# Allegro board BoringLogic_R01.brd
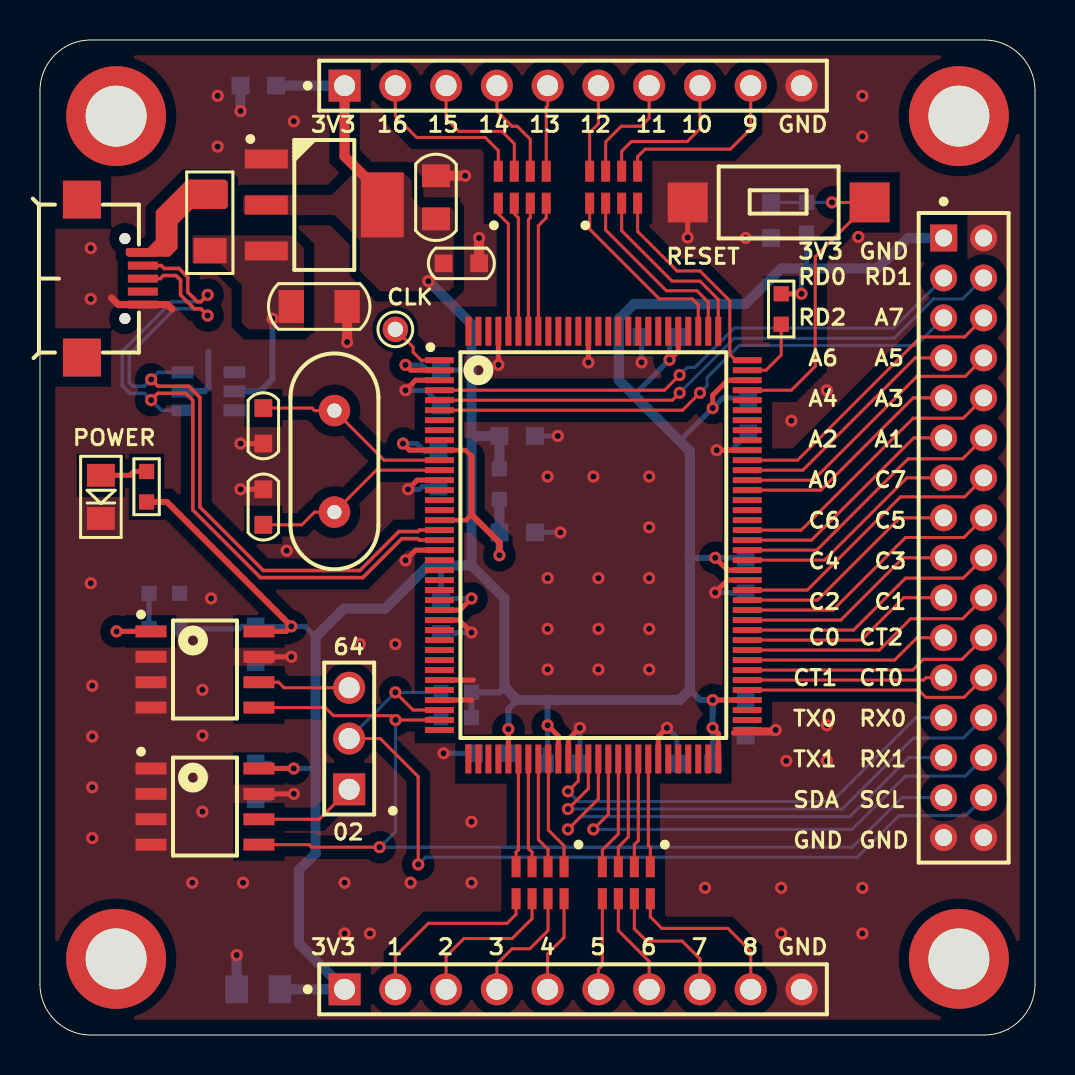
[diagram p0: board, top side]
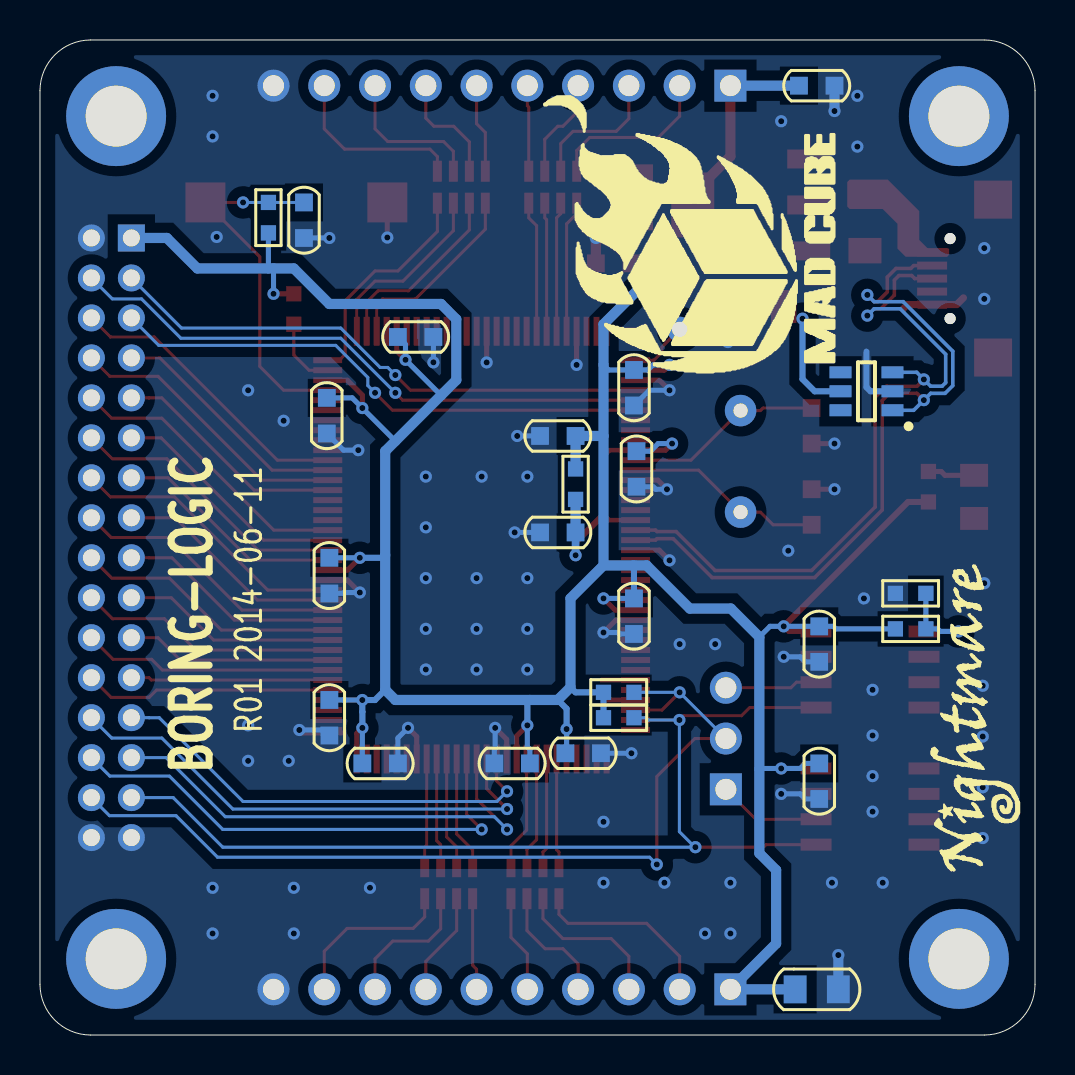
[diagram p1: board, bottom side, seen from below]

Outline 49.78 x 49.78 mm; copper layers: TOP, BOTTOM. Coordinates in mm from the lower left corner of the outline.
Outline path: 0,47.24 0,2.54 arc(0.74,0.74) 2.54,0 47.24,0 arc(49.04,0.74) 49.78,2.54 49.78,47.24 arc(49.04,49.04) 47.24,49.78 2.54,49.78 arc(0.74,49.04) 0,47.24

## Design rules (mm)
net group DIFF_USB: nets USB_DM USB_DP

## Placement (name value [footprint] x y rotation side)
C1  0.1uF  [C0603]  10.79 12.7 180 bottom
C2  22uF  [C1206]  13.97 36.45 90 top
C3  10uF  [C0805]  19.81 41.91 180 top
C4  0.1uF  [C0603]  21.08 38.61 90 top
C5  22pF  [C0603]  11.18 26.42 0 top
C6  0.1uF NC  [C0603]  10.79 19.56 180 bottom
C7  22pF  [C0603]  11.18 30.48 180 top
C8  1uF  [C0603]  36.58 40.77 0 bottom
C9  10uF  [C0805]  10.92 2.29 90 bottom
C10  0.1uF  [C0603]  10.92 47.5 90 bottom
C11  0.1uF  [C0603]  35.31 22.99 180 bottom
C12  0.1uF  [C0603]  22.61 14.1 90 bottom
C13  0.1uF  [C0603]  30.99 34.92 90 bottom
C14  0.1uF  [C0603]  20.07 32.38 180 bottom
C15  0.1uF  [C0603]  26.16 13.59 270 bottom
C16  0.1uF  [C0603]  35.43 30.99 180 bottom
C17  0.1uF  [C0603]  20.07 20.95 180 bottom
C18  0.1uF  [C0603]  32.77 13.59 90 bottom
C19  0.1uF  [C0603]  35.31 15.88 180 bottom
C20  1uF  [C0603]  23.88 29.97 270 bottom
C21  0.1uF  [C0603]  23.88 25.15 270 bottom
C22  0.1uF  [C0603]  19.94 28.32 180 bottom
D1  SRV05 NC  [SOT23-6]  8.43 32.21 0 bottom
F1  1.5A  [R1206]  8.51 40.64 0 top
FB1  120R  [R0603]  22.99 28.32 270 bottom
J1  LOGIC_CON_A  [SIP10]  15.24 2.29 0 top
J2  LOGIC_CON_B  [SIP10]  15.24 47.5 0 top
J3  EXT_IOA  [SIP16X2_2MM]  45.21 39.88 270 top
J4  JUMPER  [SIP3]  15.47 12.29 90 top
LED1  PWR  [LED0805]  3.05 26.92 0 top
NOREF  -  []  7.52 30.63 90 bottom
NOREF#2  -  []  3.15 15.57 90 bottom
P1  MicroUSB Female  [USB_MICRO_F_SMT]  -0.05 37.85 270 top
R1  2.2K  [R0603]  20.07 17.14 0 bottom
R2  2.2K  [R0603]  20.07 15.88 0 bottom
R5  2.2K NC  [R0603]  5.46 20.32 0 bottom
R7  2.2K NC  [R0603]  6.99 22.1 180 bottom
R9  510R  [R0603]  5.33 28.19 270 top
R11  100K  [R0603]  38.35 41.66 270 bottom
R12  100K  [R0603]  37.08 35.56 90 top
RN1  100R  [RN0603]  29.34 7.62 270 top
RN2  100R  [RN0603]  25.02 7.62 270 top
RN3  100R  [RN0603]  24.13 42.42 90 top
RN4  100R  [RN0603]  28.7 42.42 90 top
SW1  RESET  [SW_2P_SMT]  36.96 41.66 0 top
TH1  TH_3mm  [TH3_0]  3.81 45.97 0 top
TH2  TH_3mm  [TH3_0]  45.97 45.97 0 top
TH3  TH_3mm  [TH3_0]  45.97 3.81 0 top
TH4  TH_3mm  [TH3_0]  3.81 3.81 0 top
TP1  VO  [TP5030]  17.78 35.31 0 top
U1  CY7C68013A  [QFP128A]  27.69 24.51 0 top
U2  AT24C02  [SO8]  8.26 11.43 0 top
U3  LM1117  [SOT223]  14.22 41.53 0 top
U4  AT24C64 NC  [SO8]  8.26 18.29 0 top
Y1  HC-49S 24M  [HC-49S]  14.73 28.7 90 top

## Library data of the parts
C1 C4-C22 = CAP NP
C2 C3 = CAP_CE_0603
D1 = SRV05-4
F1 = FUSE
FB1 = FB
J1 J2 = HEADER 10
J3 = HEADER 16X2
J4 = HEADER 3
LED1 = LED_0805
P1 = CON_USB_MICRO_F: User Part Number: pn; Tolerance: RichardLC
R1 R2 R5 R7 R9 R11 R12 = R
RN1-RN4 = 8P4R_0402
SW1 = SW PUSHBUTTON
TH1-TH4 = THROUGH_HOLE
TP1 = T POINT R
U1 = CY7C68013A_128P
U2 U4 = AT24C512
U3 = LM1117
Y1 = HC-49S

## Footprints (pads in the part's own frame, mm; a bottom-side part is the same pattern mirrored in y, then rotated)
C0603
  rect 0.889x0.889 smd: 1(0,0.889) 2(0,-0.889)
C0805
  rect 1.397x1.143 smd: 1(0,1.079) 2(0,-1.079)
C1206
  rect 1.651x1.27 smd: 1(0,1.397) 2(0,-1.397)
HC-49S
  round 1.575 hole 0.711: 1(-2.54,0) 2(2.54,0)
LED0805
  rect 1.397x1.143 smd: 1(0,1.079) 2(0,-1.079)
QFP128A
  rect 1.45x0.3 smd: 1(-7.7,9.25) 2(-7.7,8.75) 3(-7.7,8.25) 4(-7.7,7.75) 5(-7.7,7.25) 6(-7.7,6.75) 7(-7.7,6.25) 8(-7.7,5.75) 9(-7.7,5.25) 10(-7.7,4.75) 11(-7.7,4.25) 12(-7.7,3.75) 13(-7.7,3.25) 14(-7.7,2.75) 15(-7.7,2.25) 16(-7.7,1.75) 17(-7.7,1.25) 18(-7.7,0.75) 19(-7.7,0.25) 20(-7.7,-0.25) 21(-7.7,-0.75) 22(-7.7,-1.25) 23(-7.7,-1.75) 24(-7.7,-2.25) 25(-7.7,-2.75) 26(-7.7,-3.25) 27(-7.7,-3.75) 28(-7.7,-4.25) 29(-7.7,-4.75) 30(-7.7,-5.25) 31(-7.7,-5.75) 32(-7.7,-6.25) 33(-7.7,-6.75) 34(-7.7,-7.25) 35(-7.7,-7.75) 36(-7.7,-8.25) 37(-7.7,-8.75) 38(-7.7,-9.25) 65(7.7,-9.25) 66(7.7,-8.75) 67(7.7,-8.25) 68(7.7,-7.75) 69(7.7,-7.25) 70(7.7,-6.75) 71(7.7,-6.25) 72(7.7,-5.75) 73(7.7,-5.25) 74(7.7,-4.75) 75(7.7,-4.25) 76(7.7,-3.75) 77(7.7,-3.25) 78(7.7,-2.75) 79(7.7,-2.25) 80(7.7,-1.75) 81(7.7,-1.25) 82(7.7,-0.75) 83(7.7,-0.25) 84(7.7,0.25) 85(7.7,0.75) 86(7.7,1.25) 87(7.7,1.75) 88(7.7,2.25) 89(7.7,2.75) 90(7.7,3.25) 91(7.7,3.75) 92(7.7,4.25) 93(7.7,4.75) 94(7.7,5.25) 95(7.7,5.75) 96(7.7,6.25) 97(7.7,6.75) 98(7.7,7.25) 99(7.7,7.75) 100(7.7,8.25) 101(7.7,8.75) 102(7.7,9.25)
  rect 0.3x1.45 smd: 39(-6.25,-10.7) 40(-5.75,-10.7) 41(-5.25,-10.7) 42(-4.75,-10.7) 43(-4.25,-10.7) 44(-3.75,-10.7) 45(-3.25,-10.7) 46(-2.75,-10.7) 47(-2.25,-10.7) 48(-1.75,-10.7) 49(-1.25,-10.7) 50(-0.75,-10.7) 51(-0.25,-10.7) 52(0.25,-10.7) 53(0.75,-10.7) 54(1.25,-10.7) 55(1.75,-10.7) 56(2.25,-10.7) 57(2.75,-10.7) 58(3.25,-10.7) 59(3.75,-10.7) 60(4.25,-10.7) 61(4.75,-10.7) 62(5.25,-10.7) 63(5.75,-10.7) 64(6.25,-10.7) 103(6.25,10.7) 104(5.75,10.7) 105(5.25,10.7) 106(4.75,10.7) 107(4.25,10.7) 108(3.75,10.7) 109(3.25,10.7) 110(2.75,10.7) 111(2.25,10.7) 112(1.75,10.7) 113(1.25,10.7) 114(0.75,10.7) 115(0.25,10.7) 116(-0.25,10.7) 117(-0.75,10.7) 118(-1.25,10.7) 119(-1.75,10.7) 120(-2.25,10.7) 121(-2.75,10.7) 122(-3.25,10.7) 123(-3.75,10.7) 124(-4.25,10.7) 125(-4.75,10.7) 126(-5.25,10.7) 127(-5.75,10.7) 128(-6.25,10.7)
R0603
  rect 0.762x0.762 smd: 1(0,0) 2(1.524,0)
R1206
  rect 1.651x1.27 smd: 1(0,1.397) 2(0,-1.397)
RN0603
  rect 1.05x0.45 smd: 1(-0.8,1.2) 2(-0.8,0.4) 3(-0.8,-0.4) 4(-0.8,-1.2) 5(0.8,-1.2) 6(0.8,-0.4) 7(0.8,0.4) 8(0.8,1.2)
SIP3
  rect 1.6x1.6 hole 1.05: 1(0,0)
  round 1.6 hole 1.05: 2(2.54,0) 3(5.08,0)
SIP10
  rect 1.6x1.6 hole 1.05: 1(0,0)
  round 1.6 hole 1.05: 2(2.54,0) 3(5.08,0) 4(7.62,0) 5(10.16,0) 6(12.7,0) 7(15.24,0) 8(17.78,0) 9(20.32,0) 10(22.86,0)
SIP16X2_2MM
  rect 1.35x1.35 hole 0.85: 1(0,0)
  round 1.35 hole 0.85: 2(0,2) 3(2,0) 4(2,2) 5(4,0) 6(4,2) 7(6,0) 8(6,2) 9(8,0) 10(8,2) 11(10,0) 12(10,2) 13(12,0) 14(12,2) 15(14,0) 16(14,2) 17(16,0) 18(16,2) 19(18,0) 20(18,2) 21(20,0) 22(20,2) 23(22,0) 24(22,2) 25(24,0) 26(24,2) 27(26,0) 28(26,2) 29(28,0) 30(28,2) 31(30,0) 32(30,2)
SO8
  rect 1.55x0.6 smd: 1(-2.7,1.905) 2(-2.7,0.635) 3(-2.7,-0.635) 4(-2.7,-1.905) 5(2.7,-1.905) 6(2.7,-0.635) 7(2.7,0.635) 8(2.7,1.905)
SOT23-6
  rect 1.1x0.6 smd: 1(-1.3,0.95) 2(-1.3,0) 3(-1.3,-0.95) 4(1.3,-0.95) 5(1.3,0) 6(1.3,0.95)
SOT223
  rect 2.15x0.95 smd: 1(-2.9,2.3) 2(-2.9,0) 3(-2.9,-2.3)
  rect 2.15x3.25 smd: 4(2.9,0)
SW_2P_SMT
  rect 2x2 smd: 1(-4.55,0) 2(4.55,0)
TH3_0
  round 5 hole 3.048: 1(0,0)
TP5030
  round 1.27 hole 0.76: 1(0,0)
USB_MICRO_F_SMT
  round 0.55 hole 0.55: (-2,4.3) (2,4.3)
  rect 0.4x1.5 smd: 1(-1.3,5.2) 2(-0.65,5.2) 3(0,5.2) 4(0.65,5.2) 5(1.3,5.2)
  rect 1.9x1.9 smd: 6(-3.95,2.15) 7(3.95,2.15)

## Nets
GND: C1.2 C2.2 C3.2 C4.2 C5.1 C6.2 C7.1 C8.1 C9.2 C10.2 C11.2 C12.2 C13.2 C14.2 C15.2 C16.2 C17.2 C18.2 C19.2 C20.2 C21.2 C22.2 D1.2(GND) J1.10 J2.10 J3.2 J3.31 J3.32 LED1.2(CATHODE) P1.5(GND) R7.1 SW1.1 U1.3(GND#3) U1.13(AGND#13) U1.20(AGND#20) U1.27(GND#27) U1.33(RSVD) U1.35(EA) U1.49(GND#49) U1.58(GND#58) U1.65(GND#65) U1.80(GND#80) U1.93(GND#93) U1.116(GND#116) U1.125(GND#125) U2.1(A0) U2.2(A1) U2.3(NC) U2.4(GND) U2.7(WP) U3.1(GND) U4.2(A1) U4.3(NC) U4.4(GND) U4.7(WP)
VCC3V3A: C21.1 C22.1 FB1.2 U1.10(AVCC#10) U1.17(AVCC#17)
VDD3V3: C1.1 C3.1 C4.1 C6.1 C9.1 C10.1 C11.1 C12.1 C13.1 C14.1 C15.1 C16.1 C17.1 C18.1 C19.1 C20.1 FB1.1 J1.1 J2.1 J3.1 R1.2 R2.2 R5.2 R9.2 R11.2 R12.2 U1.2(VCC#2) U1.26(VCC#26) U1.43(VCC#43) U1.48(VCC#48) U1.64(VCC#64) U1.68(VCC#68) U1.81(VCC#81) U1.100(VCC#100) U1.107(VCC#107) U2.8(VCC) U3.2(OUT) U3.4(PAD) U4.8(VCC)
VDD5V: C2.1 D1.5(VCC) F1.2 U3.3(IN)
CH1: J1.2 RN2.5
CH2: J1.3 RN2.6(5)
CH3: J1.4 RN2.7(5)
CH4: J1.5 RN2.8(5)
CH5: J1.6 RN1.5
CH6: J1.7 RN1.6(5)
CH7: J1.8 RN1.7(5)
CH8: J1.9 RN1.8(5)
CH9: J2.9 RN4.5
CH10: J2.8 RN4.6(5)
CH11: J2.7 RN4.7(5)
CH12: J2.6 RN4.8(5)
CH13: J2.5 RN3.5
CH14: J2.4 RN3.6(5)
CH15: J2.3 RN3.7(5)
CH16: J2.2 RN3.8(5)
CLKOUT: TP1.1(TP) U1.1(CLKOUT)
CTL0: J3.24 U1.69(CTL0/FLAGA)
CTL1: J3.23 U1.70(CTL1/FLAGB)
CTL2: J3.22 U1.71(CTL2/FLAGC)
FD0: RN2.4 U1.44(PB0/FD0)
FD1: RN2.3(4) U1.45(PB1/FD1)
FD2: RN2.2(4) U1.46(PB2/FD2)
FD3: RN2.1(4) U1.47(PB3/FD3)
FD4: RN1.4 U1.54(PB4/FD4)
FD5: RN1.3(4) U1.55(PB5/FD5)
FD6: RN1.2(4) U1.56(PB6/FD6)
FD7: RN1.1(4) U1.57(PB7/FD7)
FD8: RN4.4 U1.102(PD0/FD8)
FD9: RN4.3(4) U1.103(PD1/FD9)
FD10: RN4.2(4) U1.104(PD2/FD10)
FD11: RN4.1(4) U1.105(PD3/FD11)
FD12: RN3.4 U1.121(PD4/FD12)
FD13: RN3.3(4) U1.122(PD5/FD13)
FD14: RN3.2(4) U1.123(PD6/FD14)
FD15: RN3.1(4) U1.124(PD7/FD15)
PA0: J3.13 U1.82(PA0/I\N\T\0\)
PA1: J3.12 U1.83(PA1/I\N\T\1\)
PA2: J3.11 U1.84(PA2/SLOE)
PA3: J3.10 U1.85(PA3/WU2)
PA4: J3.9 U1.89(PA4/FIFOADR0)
PA5: J3.8 U1.90(PA5/FIFOADR1)
PA6: J3.7 U1.91(PA6/PKTEND)
PA7: J3.6 U1.92(PA7/FLAGD/S\L\C\S\)
PC0: J3.21 U1.72(PC0/GPIFADR0)
PC1: J3.20 U1.73(PC1/GPIFADR1)
PC2: J3.19 U1.74(PC2/GPIFADR2)
PC3: J3.18 U1.75(PC3/GPIFADR3)
PC4: J3.17 U1.76(PC4/GPIFADR4)
PC5: J3.16 U1.77(PC5/GPIFADR5)
PC6: J3.15 U1.78(PC6/GPIFADR6)
PC7: J3.14 U1.79(PC7/GPIFADR7)
RDY0: J3.3 U1.4(RDY0/SLRD)
RDY1: J3.4 U1.5(RDY1/SLWR)
RDY2: J3.5 U1.6(RDY2)
RESET#: C8.2 R11.1 SW1.2 U1.99(R\E\S\E\T\)
RXD0: J3.26 U1.51(RXD0)
RXD1: J3.28 U1.53(RXD1)
SCL: J3.30 J4.2 R1.1 U1.36(SCL)
SCL_LG: J4.3 U4.6(SCL)
SCL_S: J4.1 U2.6(SCL)
SDA: J3.29 R2.1 U1.37(SDA) U2.5(SDA) U4.5(SDA)
TXD0: J3.25 U1.50(TXD0)
TXD1: J3.27 U1.52(TXD1)
USB_DM: D1.1(IO1) P1.2(D-) U1.19(DMINUS)
USB_DP: D1.3(IO2) P1.3(D+) U1.18(DPLUS)
WAKEUP: R12.1 U1.101(WAKEUP)
XIN: C5.2 U1.12(XTALIN) Y1.1
XOUT: C7.2 U1.11(XTALOUT) Y1.2
N1173626: F1.1 P1.1(VCC)
N1191686: R5.1 R7.2 U4.1(A0)
N1227883: LED1.1(ANODE) R9.1

Pads without a net: D1 4 6; P1 4 6 7; TH1 1; TH2 1; TH3 1; TH4 1; U1 7 8 9 14 15 16 21 22 23 24 25 28 29 30 31 32 34 38 39 40 41 42 59 60 61 62 63 66 67 86 87 88 94 95 96 97 98 106 108 109 110 111 112 113 114 115 117 118 119 120 126 127 128

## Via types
v1: diameter 0.61, hole 0.305, TOP to BOTTOM, 111 vias

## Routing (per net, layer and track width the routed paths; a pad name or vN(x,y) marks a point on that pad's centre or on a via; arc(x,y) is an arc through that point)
GND: length 70.3
  TOP w0.254: U1.65 v1(36.81,15.26) 36.66,15.11 34.7,15.11 ; U1.20 18.8,24.26 v1(18.29,23.75) ; U1.58 30.94,14.93 v1(31.37,15.37) ; SW1.1 v1(32.41,39.9) ; v1(18.29,32.26) 18.79,32.76 U1.3 ; U1.116 v1(27.44,33.65) ; v1(18.41,27.3) 18.87,27.76 U1.13 ; U2.7 v1(12.7,12.06) ; v1(27.01,15.37) 26.44,14.79 U1.49 ; U1.35 21.59,16.76 ; U1.80 34.4,22.76 v1(33.78,22.14) ; U4.7 v1(12.57,18.92) ; C7.1 v1(10.03,29.59) ; U1.93 v1(33.86,29.26) ; U1.125 v1(22.94,33.53) ; v1(21.59,20.14) 20.97,20.76 U1.27 ; C5.1 v1(10.03,27.3) ; U1.33 21.69,17.76
  TOP w0.356: 3.58,36.88 3.92,36.55 P1.5 6.38,36.55 6.6,36.32
  TOP w0.508: C2.2 v1(15.37,34.67) ; C4.2 v1(21.97,39.88) ; C3.2 v1(21.27,42.99)
  BOTTOM w0.254: C16.2 34.6,29.26 v1(33.86,29.26) ; v1(31.37,15.37) 31.88,14.86 C18.2 ; v1(27.01,15.37) 27.01,14.33 27.05,14.29 C15.2 ; 21.72,14.1 v1(20.19,14.1) ; C11.2 34.6,22.1 34.56,22.14 v1(33.78,22.14) ; C1.2 11.5,11.81 11.75,12.06 v1(12.7,12.06) ; C20.2 v1(25.91,29.97) ; C6.2 11.5,18.67 11.75,18.92 v1(12.57,18.92) ; C19.2 35.58,15.26 v1(36.81,15.26) ; C17.2 20.77,20.07 20.84,20.14 v1(21.59,20.14) ; C13.2 v1(30.1,33.66) ; C8.1 v1(35.31,39.88) ; v1(18.29,32.26) 19.3,32.26 C14.2 ; C21.2 v1(26.04,25.15) ; v1(18.41,27.3) 18.98,27.3 19.1,27.43 C22.2
  BOTTOM w0.305: D1.2 8.23,32.21 8.43,32.41 8.43,34.19
  BOTTOM w0.508: 10.03,47.5 v1(10.03,46.23) ; C9.2 v1(9.84,4)
  vias: v1(2.54,39.37) v1(2.54,36.83) v1(2.54,22.61) v1(2.62,17.48) v1(2.62,14.94) v1(2.62,12.4) v1(2.62,9.86) v1(7.62,7.62) v1(8.13,17.27) v1(8.13,14.99) v1(8.13,12.95) v1(8.13,11.18) v1(8.56,21.84) v1(8.89,46.99) v1(8.89,44.45) v1(10.16,7.62) v1(12.34,24.23) v1(12.7,45.72) v1(15.24,7.62) v1(15.24,5.08) v1(16,19.56) v1(16.51,5.08) v1(17.78,19.56) v1(18.54,7.62) v1(21.59,10.67) v1(21.59,7.62) v1(25.4,27.94) v1(25.4,22.86) v1(25.4,20.32) v1(25.4,18.29) v1(27.69,27.94) v1(27.94,22.86) v1(27.94,20.32) v1(27.94,18.29) v1(30.48,27.94) v1(30.48,25.4) v1(30.48,22.86) v1(30.48,20.32) v1(30.48,18.29) v1(33.27,7.37) v1(37.08,7.37) v1(37.08,5.08) v1(37.34,13.72) v1(37.59,30.73) v1(39.37,32.26) v1(39.37,15.49) v1(39.37,13.72) v1(40.94,39.93) v1(41.15,46.99) v1(41.15,44.96) v1(41.15,7.37) v1(41.15,5.08)
VCC3V3A: length 15.7
  TOP w0.229: 21.59,28.96 21.28,29.26 U1.10 ; U1.17 21.32,25.76 21.59,26.04
  TOP w0.254: v1(18.16,29.59) 18.49,29.26 U1.10
  TOP w0.305: 21.59,28.96 21.59,26.04 22.99,24.64 v1(22.99,24)
  BOTTOM w0.254: C22.1 19.24,29.21 18.86,29.59 v1(18.16,29.59)
  BOTTOM w0.381: C21.1 v1(22.99,24)
  BOTTOM w0.508: C21.1 FB1.2
VDD3V3: length 191.5
  TOP w0.254: v1(21.59,21.84) 21.01,21.26 U1.26 ; v1(33.66,31.37) 33.66,32.01 34.4,32.76 U1.100 ; R12.2 v1(38.1,37.08) ; U1.81 34.4,23.26 v1(33.78,23.88) ; U1.68 v1(33.66,16.76) ; U4.8 12.32,20.19 v1(12.57,20.45) ; U1.2 18.55,33.26 v1(18.29,33.53) ; 10.96,13.34 v1(12.7,13.34) ; v1(33.66,15.37) 33.94,15.09 U1.64 ; U1.48 25.94,14.96 v1(25.4,15.49) ; v1(31.5,33.78) 31.94,34.22 U1.107 ; U1.43 v1(23.44,15.31)
  TOP w0.305: v1(12.57,20.45) 6.35,26.67 R9.2
  TOP w0.508: U3.4 17.12,42.08 15.24,43.96 J2.1
  BOTTOM w0.254: 21.59,33.53 21.34,33.27 C14.1 19.36,33.27 19.11,33.53 v1(18.29,33.53) ; v1(38.1,37.08) 38.1,38.35 ; v1(23.44,15.31) 23.44,14.16 C12.1 ; 32,29.72 v1(33.66,31.37) 34.16,31.88 C16.1 ; v1(33.78,23.88) C11.1 ; R11.2 38.35,38.35 ; 13.79,19.91 13.26,20.45 v1(12.57,20.45) C6.1 10.09,20.45 9.97,20.32 R5.2 ; 13.79,13.31 13.77,13.34 v1(12.7,13.34) 11.75,13.34 11.5,13.59 C1.1 ; C15.1 25.27,14.29 25.4,14.42 v1(25.4,15.49) ; 29.72,32 v1(31.5,33.78) 31.5,34.54 C13.1 ; v1(33.66,15.37) C18.1 ; v1(21.59,21.84) C17.1 ; C19.1 34.6,16.76 34.6,16.76 v1(33.66,16.76)
  BOTTOM w0.305: v1(33.66,15.37) 33.66,16.17 33.66,16.17 v1(33.66,16.76) 33.02,16.76 32.51,17.27 ; C17.1 20.07,23.5 ; 23.24,17.4 22.99,17.14 R1.2 R2.2 ; 23.88,16.76 23.44,16.32 v1(23.44,15.31) ; 25.27,16.76 25.4,16.64 v1(25.4,15.49) ; v1(33.78,23.88) 32.64,23.88 32.51,24
  BOTTOM w0.508: 21.59,23.5 21.59,29.97 ; 21.59,23.5 19.43,23.5 17.27,21.34 15.21,21.34 13.79,19.91 13.79,9.09 12.95,8.26 12.95,4.57 J1.1 C9.1 ; 21.59,23.5 23.24,21.84 23.24,17.4 23.88,16.76 32,16.76 32.51,17.27 32.51,29.21 28.96,32.77 28.96,35.81 29.72,36.58 35.31,36.58 37.08,38.35 41.91,38.35 43.43,39.88 J3.1 ; 21.59,29.97 C20.1 FB1.1 ; 21.59,29.97 21.59,35.56 v1(19.43,37.72) ; C10.1 J2.1
VDD5V: length 5.2
  BOTTOM w0.305: v1(11.63,35.84) 11.63,32.82 11.02,32.21 D1.5
CH1: length 9.3
  TOP w0.152: J1.2 17.78,3.94 19.43,5.59 23.37,5.59 23.82,6.04 RN2.5
CH2: length 7.7
  TOP w0.152: J1.3 20.32,3.94 21.21,4.83 23.62,4.83 24.62,5.82 RN2.6
CH3: length 6.1
  TOP w0.152: RN2.7 25.42,5.23 24.51,4.32 23.62,4.32 22.86,3.56 J1.4
CH4: length 4.9
  TOP w0.152: RN2.8 26.22,4.88 25.4,4.06 J1.5
CH5: length 4.6
  TOP w0.152: RN1.5 28.14,3.49 27.94,3.29 J1.6
CH6: length 5.2
  TOP w0.152: J1.7 30.48,3.68 28.94,5.23 RN1.6
CH7: length 6.9
  TOP w0.152: RN1.7 29.74,5.31 30.35,4.7 32.13,4.7 33.02,3.81 J1.8
CH8: length 8.5
  TOP w0.152: RN1.8 30.54,5.91 31.11,5.33 34.42,5.33 35.56,4.19 J1.9
CH9: length 9.1
  TOP w0.152: J2.9 35.56,45.34 34.54,44.32 30.28,44.32 29.9,43.95 RN4.5
CH10: length 7.5
  TOP w0.152: J2.8 33.02,45.34 32.38,44.7 29.59,44.7 29.1,44.22 RN4.6
CH11: length 5.8
  TOP w0.152: RN4.7 28.3,44.68 29.08,45.47 30.07,45.47 30.48,45.87 J2.7
CH12: length 4.5
  TOP w0.152: J2.6 27.94,45.59 27.5,45.16 RN4.8
CH13: length 4.3
  TOP w0.152: RN3.5 25.33,46.42 25.4,46.49 J2.5
CH14: length 5.1
  TOP w0.152: RN3.6 24.53,44.81 23.88,45.47 23.62,45.47 22.86,46.23 J2.4
CH15: length 7
  TOP w0.152: RN3.7 23.73,44.6 23.11,45.21 20.95,45.21 20.32,45.85 J2.3
CH16: length 8.4
  TOP w0.152: RN3.8 22.93,44.25 22.28,44.91 18.85,44.91 17.78,45.97 J2.2
CLKOUT: length 3
  TOP w0.152: TP1.1 18.67,34.42 18.67,34.16 19.07,33.76 U1.1
CTL0: length 12.4
  TOP w0.152: J3.24 46.22,16.89 44.32,16.89 43.95,17.26 U1.69
CTL1: length 9.9
  TOP w0.152: J3.23 44.33,17.88 44.21,17.76 U1.70
CTL2: length 12.5
  TOP w0.152: J3.22 46.13,18.8 44.2,18.8 43.66,18.26 U1.71
FD0: length 5.4
  TOP w0.152: RN2.4 23.82,9.15 23.94,9.27 U1.44
FD1: length 5.5
  TOP w0.152: U1.45 24.44,9.33 24.62,9.15 RN2.3
FD2: length 5.6
  TOP w0.152: U1.46 24.94,9.77 25.42,9.29 RN2.2
FD3: length 5.7
  TOP w0.152: RN2.1 26.22,9.47 25.44,10.25 U1.47
FD4: length 5.7
  TOP w0.152: U1.54 28.94,10.06 28.14,9.26 RN1.4
FD5: length 5.6
  TOP w0.152: U1.55 29.44,9.91 28.94,9.41 RN1.3
FD6: length 5.5
  TOP w0.152: U1.56 29.94,9.72 29.74,9.53 RN1.2
FD7: length 5.4
  TOP w0.152: RN1.1 30.54,9.4 30.44,9.5 U1.57
FD8: length 11.1
  TOP w0.152: RN4.4 29.9,40.2 31.88,38.23 33.02,38.23 34.51,36.73 34.51,34.06 34.81,33.76 U1.102
FD9: length 9.2
  TOP w0.152: RN4.3 29.1,40.24 31.62,37.72 33.02,37.72 33.94,36.8 U1.103
FD10: length 9.4
  TOP w0.152: U1.104 33.44,36.67 32.87,37.24 31.34,37.24 28.3,40.28 RN4.2
FD11: length 9.6
  TOP w0.152: U1.105 32.94,36.53 32.64,36.83 30.99,36.83 27.5,40.32 RN4.1
FD12: length 6.6
  TOP w0.152: U1.121 24.94,40.49 25.33,40.89 RN3.4
FD13: length 6.4
  TOP w0.152: U1.122 24.44,40.79 24.53,40.89 RN3.3
FD14: length 6.5
  TOP w0.152: U1.123 23.94,40.89 23.73,41.09 RN3.2
FD15: length 6.6
  TOP w0.152: RN3.1 22.93,41.09 23.44,40.58 U1.124
PA0: length 11.5
  TOP w0.152: J3.13 43.37,27.88 39.25,23.76 U1.82
PA1: length 14.2
  TOP w0.152: J3.12 46.16,28.83 43.43,28.83 38.87,24.26 U1.83
PA2: length 11.9
  TOP w0.152: J3.11 43.72,29.88 38.6,24.76 U1.84
PA3: length 14.6
  TOP w0.152: J3.10 46.19,30.86 43.69,30.86 38.09,25.26 U1.85
PA4: length 11.7
  TOP w0.152: J3.9 44.33,31.88 44.33,31.88 43.69,31.88 39.07,27.26 U1.89
PA5: length 14.4
  TOP w0.152: U1.90 38.68,27.76 43.88,32.96 46.29,32.96 J3.8
PA6: length 12.2
  TOP w0.152: J3.7 43.78,33.88 38.17,28.26 U1.91
PA7: length 14.8
  TOP w0.152: J3.6 46.26,34.92 44.07,34.92 37.9,28.76 U1.92
PC0: length 10.3
  TOP w0.152: U1.72 42.76,18.76 43.88,19.88 J3.21
PC1: length 12.9
  TOP w0.152: J3.20 46.16,20.83 43.56,20.83 41.99,19.26 U1.73
PC2: length 10.7
  TOP w0.152: J3.19 43.21,21.88 41.1,19.76 U1.74
PC3: length 13.3
  TOP w0.152: J3.18 46.19,22.86 43.31,22.86 40.71,20.26 U1.75
PC4: length 11.1
  TOP w0.152: J3.17 44.33,23.88 44.33,23.88 43.18,23.88 40.06,20.76 U1.76
PC5: length 13.7
  TOP w0.152: J3.16 46.23,24.89 43.31,24.89 39.68,21.26 U1.77
PC6: length 11.5
  TOP w0.152: J3.15 43.02,25.88 38.91,21.76 U1.78
PC7: length 14.2
  TOP w0.152: U1.79 38.39,22.26 43.05,26.92 46.26,26.92 J3.14
RDY0: length 27.6
  TOP w0.152: U1.4 31.25,32.26 v1(32,33.02)
  BOTTOM w0.152: J3.3 42.7,35.37 34.73,35.37 32.77,33.4 32.38,33.4 v1(32,33.02)
RDY1: length 29.8
  TOP w0.152: U1.5 31.63,31.76 v1(32,32.13)
  BOTTOM w0.152: v1(32,32.13) 34.73,34.86 42.74,34.86 44.7,36.83 46.16,36.83 J3.4
RDY2: length 27.4
  TOP w0.152: v1(33.02,32.13) 32.15,31.26 U1.6
  BOTTOM w0.152: J3.5 43.84,34.51 34.99,34.51 33.38,32.9 33.38,32.49 v1(33.02,32.13)
RESET#: length 18.2
  TOP w0.152: v1(39.62,41.66) SW1.2 38.79,38.94 38.79,33.45 37.6,32.26 U1.99
  BOTTOM w0.152: v1(39.62,41.66) R11.1 C8.2
RXD0: length 25.6
  TOP w0.152: U1.51 27.44,12.33 v1(26.42,11.31)
  BOTTOM w0.152: J3.26 46.19,14.86 43.69,14.86 40.14,11.31 v1(26.42,11.31)
RXD1: length 24.8
  TOP w0.152: U1.53 28.44,11.04 v1(27.69,10.29)
  BOTTOM w0.152: J3.28 46.29,12.95 43.31,12.95 40.64,10.29 v1(27.69,10.29)
SCL: length 46.4
  TOP w0.152: U1.36 18.66,16.26 v1(17.78,17.14) ; J4.2 17.02,14.83 18.92,12.93 v1(18.92,8.53)
  BOTTOM w0.152: R1.1 v1(17.78,17.14) J4.2 ; J3.30 46.31,10.97 42.98,10.97 40.9,8.9 19.28,8.9 v1(18.92,8.53)
SCL_LG: length 4.6
  TOP w0.152: J4.3 12.22,17.37 11.94,17.65 U4.6
SCL_S: length 5.1
  TOP w0.152: J4.1 13.97,10.79 U2.6
SDA: length 53.6
  TOP w0.152: U1.37 v1(17.79,15.76) 17.58,15.98 14.68,15.98 14.27,16.38 U4.5 ; v1(16.99,9.4) 13.59,9.4 13.46,9.53 U2.5
  BOTTOM w0.152: 17.02,9.4 40.64,9.4 43.12,11.88 J3.29 ; 17.02,9.4 v1(16.99,9.4) ; 17.02,9.4 17.79,10.17 v1(17.79,15.76) 19.36,15.76 19.48,15.88 R2.1
TXD0: length 22.6
  TOP w0.152: U1.50 26.94,12.71 v1(26.42,12.19)
  BOTTOM w0.152: J3.25 44.33,15.88 44.33,15.88 43.81,15.88 39.62,11.68 26.92,11.68 v1(26.42,12.19)
TXD1: length 24.4
  TOP w0.152: U1.52 27.94,11.81 v1(26.42,10.29)
  BOTTOM w0.152: J3.27 43.47,13.88 40.51,10.92 27.05,10.92 v1(26.42,10.29)
USB_DM: length 37.7
  TOP w0.178: P1.2 6.07,38.5 6.21,38.35 6.95,38.35 7.39,37.92 7.39,37.17 7.87,36.69 8.05,36.69 v1(8.39,37.03) ; v1(5.56,31.77) 5.9,32.11 7.29,32.11 7.65,31.75 7.65,26.27 11.03,22.89 16.15,22.89 18.1,24.83 18.92,24.83 18.99,24.76 U1.19
  BOTTOM w0.178: v1(8.39,37.03) 8.05,36.69 6.6,36.69 4.11,34.21 4.11,32.49 4.5,32.11 5.22,32.11 v1(5.56,31.77) 6.07,31.26 D1.1
USB_DP: length 36.5
  TOP w0.178: P1.3 6.02,37.85 6.17,38 6.81,38 7.04,37.77 7.04,37.02 7.72,36.33 8.05,36.33 v1(8.39,35.99) ; U1.18 18.99,25.26 18.92,25.19 17.95,25.19 16.01,23.24 11.18,23.24 8,26.42 8,31.9 7.44,32.46 5.9,32.46 v1(5.56,32.8)
  BOTTOM w0.178: D1.3 5.92,33.16 v1(5.56,32.8) 5.22,32.46 4.65,32.46 4.47,32.64 4.47,34.06 6.74,36.33 8.05,36.33 v1(8.39,35.99)
WAKEUP: length 3.6
  TOP w0.152: U1.101 36.32,33.26 37.08,34.02 R12.1
XIN: length 9.9
  TOP w0.152: C5.2 13.1,25.53 13.74,26.16 Y1.1 16.83,28.26 U1.12
XOUT: length 9.9
  TOP w0.152: C7.2 13.61,31.37 13.74,31.24 Y1.2 17.21,28.76 U1.11
N1191686: length 5.2
  TOP w0.254: U4.1 v1(3.83,20.19)
  BOTTOM w0.254: R7.2 R5.1 4.87,20.32 4.75,20.19 v1(3.83,20.19)
N1227883: length 2.4
  TOP w0.254: LED1.1 4.51,28 4.7,28.19 R9.1

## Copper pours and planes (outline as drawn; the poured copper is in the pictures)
GND on TOP: 2.54,0.76 1.28,1.28 0.76,2.54 0.76,47.24 1.28,48.5 2.54,49.02 47.24,49.02 48.5,48.5 49.02,47.24 49.02,2.54 48.5,1.28 47.24,0.76 ; 24 cut-outs
GND on BOTTOM: 2.54,0.76 1.28,1.28 0.76,2.54 0.76,47.24 1.28,48.5 2.54,49.02 47.24,49.02 48.5,48.5 49.02,47.24 49.02,2.54 48.5,1.28 47.24,0.76 ; 8 cut-outs
VDD3V3 on TOP: 10.29,42.04 14.61,42.04 15.75,43.18 18.16,43.18 18.67,42.67 18.67,41.78 19.05,41.4 20.57,41.4 20.7,41.27 20.7,37.47 20.45,37.21 17.02,37.21 16,38.23 16,39.75 14.73,41.02 10.29,41.02 10.16,41.15 10.16,41.91
VDD5V on TOP: 13.21,39.37 13.21,35.43 13.08,35.31 10.41,35.31 10.1,35.62 10.1,37.53 9.02,38.61 7.62,38.61 7.62,40.01 12.57,40.01
N1173626 on TOP (solid shape): 9.4,42.67 9.4,41.45 9.27,41.33 7.62,41.33 6.88,40.59 6.88,39.34 6.48,38.94 4.39,38.94 4.29,39.04 4.29,39.32 4.34,39.37 5.38,39.37 5.79,39.78 5.79,41.22 7.37,42.8 9.27,42.8

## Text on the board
Ref Des/Silkscreen Bottom: R01 2014-06-11 | BORING-LOGIC
Ref Des/Silkscreen Top: POWER | 3V3 | 02 | 64 | 16 | CLK | 1 | 15 | 2 | 14 | 3 | 13 | 4 | 12 | 5 | 11 | 6 | RESET | 10 | 7 | 9 | 8 | GND | CT1 | TX0 | TX1 | SDA | RD0 | RD2 | A6 | A4 | A2 | A0 | C6 | C4 | C2 | C0 | CT2 | CT0 | RX0 | RX1 | SCL | RD1 | A7 | A5 | A3 | A1 | C7 | C5 | C3 | C1
